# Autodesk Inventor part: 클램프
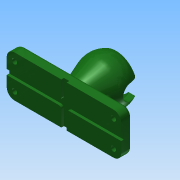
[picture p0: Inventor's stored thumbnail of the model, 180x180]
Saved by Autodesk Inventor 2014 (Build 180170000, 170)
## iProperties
Created: 2017-10
Part Number: 클램프
Material: ABS 플라스틱
Document SubType Name: Modeling
Designer: mduedu
Density: 1.06 g/cm^3
Mass: 4.60308 g
Surface Area: 31.9266 cm^2
Volume: 4.34252 cm^3
Appearance: 매끄러움 - 짙은 산림 녹색
Author: mduedu
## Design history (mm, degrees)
sketch "스케치1"
  geometry: L1 (-22, -8)-(22, -8); L2 (22, -8)-(22, 8); L3 (22, 8)-(-22, 8); L4 (-22, 8)-(-22, -8); L5 (-22, -8)-(22, 8); L6 (22, -8)-(-22, 8); 1 further point
  constraints: 12 end point, 2 midpoint, 2 parallel, 1 horizontal, 1 perpendicular
  dimensions: "d0" = 44 distance of L3.end L2.end; "d1" = 16 distance of L2.end L1.end
extrude "돌출1" new body sketch "스케치1" distance "d2" = 4; taper "d3" = 0 deg
sketch "스케치2"
  geometry: L1 (9, -12)-(-9, -12); L2 (-8, 0)-(8, 0) reference; A1 r 9 centre (0, -12) between (9, -12) and (-9, -12); 3 further points
  constraints: 3 midpoint, 2 end point, 2 point on circle, 1 centre point, 1 horizontal, 1 vertical alignment
  dimensions: "d4" = 18 diameter of A1; "d6" = 12 distance from line of A1.centre L2
revolve "회전1" sketch "스케치2" stored, may be unused: angle "d5" = 90 deg
sketch "스케치6"
  geometry: L1 (0, 0)-(0, -12); L2 (0, -12)-(9, -12); L3 (5, 0)-(8.391, -8.746); L4 (0, 0)-(5, 0); A1 r 9 centre (0, -12) between (9, -12) and (8.391, -8.746) reference
  constraints: 8 end point, 2 point on circle, 1 parallel, 1 perpendicular, 1 tangent, 1 vertical
  dimensions: "d19" = 10 diameter of L3.start L1
revolve "회전3" sketch "스케치6" stored, may be unused: angle "d22" = 90 deg
sketch "스케치3"
  geometry: L1 (7, -12)-(-7, -12); L2 (8, 0)-(-8, 0) reference; L3 (8.062, -16)-(-8.062, -16); A1 r 7 centre (0, -12) between (7, -12) and (-7, -12); A2 r 9 centre (0, -12) between (8.062, -16) and (-8.062, -16) reference; 4 further points
  constraints: 4 end point, 4 point on circle, 3 midpoint, 1 centre point, 1 coincident, 1 concentric, 1 horizontal, 1 parallel, 1 vertical alignment
  dimensions: "d7" = 14 diameter of A1; "d10" = 4 distance between parallel lines of L3 L1
revolve "회전2" stored, may be unused: angle "d8" = 90 deg
feature "돌출 곡면2" dims "d23" = 50, "d24" = 0
feature "분할2"
node "작업점1"
sketch "스케치7"
  geometry: L1 (3, -16)-(-3, -16); L2 (-3, -16)-(-3, -13); L3 (3, -13)-(3, -16); L4 (-5.745, -16)-(5.745, -16) reference; A1 r 3 centre (0, -13) between (3, -13) and (-3, -13); 2 further points
  constraints: 6 end point, 2 point on circle, 2 tangent, 1 centre point, 1 coincident, 1 collinear, 1 horizontal, 1 parallel, 1 perpendicular, 1 vertical alignment
  dimensions: "d25" = 6 diameter of A1; "d30" = 3 distance from line of point (0, -13) L1
extrude "돌출2" cut sketch "스케치7" stored distance "d28" = 50; taper "d29" = 0 deg
fillet "모깎기1" dims "d31" = 0.5
sketch "스케치8"
  geometry: L1 (-5, 0)-(-8.391, -8.746) reference; L2 (-22, 0)-(22, 0) reference; L3 (-7.495, -6.434)-(-12, 0); 1 further point
  constraints: 2 end point, 2 point on line
  dimensions: "d32" = 12 distance of L3.end point (0, 0); "d33" = 55 deg angle of L3 L2
feature "리브1" sketch "스케치8" dims "d34" = 1, "d35" = 3, "d36" = 0, "d37" = 0, "d38" = 1, "d39" = 1
fillet "모깎기2" dims "d40" = 1
fillet "모깎기3" dims "d41" = 1
fillet "모깎기4" dims "d42" = 1
sketch "스케치9"
  geometry: L1 (22, -8)-(22, 8) reference; L2 (22, 8)-(-22, 8) reference; L3 (-22, 8)-(-22, -8) reference; L4 (-22, -8)-(22, -8) reference; L5 (-22, 1)-(22, 1); L6 (22, 1)-(22, -1); L7 (22, -1)-(-22, -1); L8 (-22, -1)-(-22, 1); L9 (-1, 8)-(1, 8); L10 (1, 8)-(1, -8); L11 (1, -8)-(-1, -8); L12 (-1, -8)-(-1, 8); 3 further points
  constraints: 16 end point, 4 parallel, 4 point on line, 2 horizontal, 2 midpoint, 2 perpendicular, 1 horizontal alignment, 1 vertical alignment
  dimensions: "d43" = 2 distance between parallel lines of L7 L5; "d45" = 2 distance between parallel lines of L10 L12
extrude "돌출3" cut sketch "스케치9" distance "d46" = 1; taper "d47" = 0 deg
fillet "모깎기5" dims "d48" = 1
fillet "모깎기6" dims "d49" = 3
fillet "모깎기7" dims "d50" = 1
sketch "스케치10"
  geometry: C1 r 1 at (-19, 5); C2 r 1 at (19, 5); C3 r 1 at (19, -5); C4 r 1 at (-19, -5); A1 r 3 centre (-19, 5) between (-19, 8) and (-22, 5) reference; A2 r 3 centre (19, 5) between (22, 5) and (19, 8) reference; A3 r 3 centre (19, -5) between (19, -8) and (22, -5) reference; A4 r 3 centre (-19, -5) between (-22, -5) and (-19, -8) reference; 1 further point
  constraints: 4 centre point, 4 coincident, 3 equal radius
  dimensions: "d51" = 2 diameter of C1
extrude "돌출4" cut sketch "스케치10" stored distance "d52" = 1; taper "d53" = 0 deg
node "솔리드1"
mirror "대칭1"
node "곡면2"
node "투영된 루프1"
